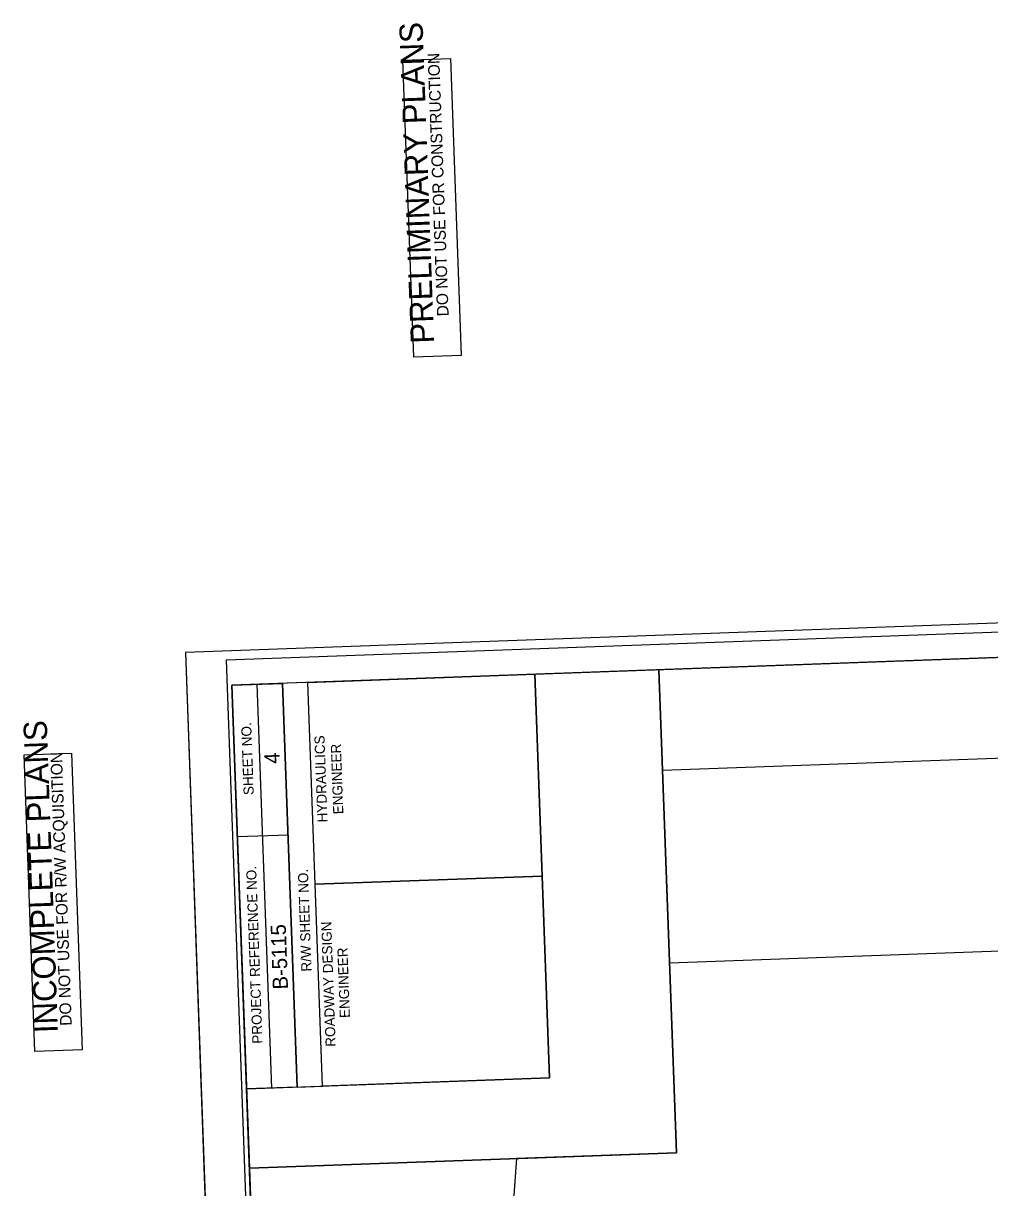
# Model space of a CAD drawing. Extents: x 2065068 to 2066582, y 144283 to 146300.
# Drawn here: x 2065347 to 2065825, y 145724 to 146300 of the extents above; entities that cross this region are included whole.
import ezdxf

# ---------------------------------------------------------------- set-up
doc = ezdxf.new("R2010")
doc.units = 0
for name, color, linetype in [('Sheet Clip Boundary CELL', 7, 'Continuous'), ('Sheet Cutting Line CELL', 7, 'Continuous'), ('Sheet Data Field CELL', 7, 'Continuous'), ('Sheet Layout Plan Border', 7, 'Continuous'), ('Sheet Plan CELL', 7, 'Continuous'), ('Sheet Plan Layout CELL', 7, 'Continuous'), ('Sheet Plot Border Inside CELL', 7, 'Continuous'), ('Sheet Plot Border Outside CELL', 7, 'Continuous'), ('Sheet Sticker Incomplete CELL', 7, 'Continuous'), ('Sheet Sticker Preliminary CELL', 7, 'Continuous')]:
    doc.layers.add(name, color=color, linetype=linetype)

msp = doc.modelspace()

# ---------------------------------------------------------------- linework, layer by layer
at = {"layer": 'Sheet Clip Boundary CELL'}
msp.add_lwpolyline([(2066209.26, 144563.12), (2066197.36, 145017.22), (2066304.56, 145076.85), (2066276.35, 145857.16), (2065667.01, 145835.13), (2065670.41, 145741.24), (2065591.32, 145738.38), (2065521, 144770.65), (2065527.51, 144606.5), (2065634.3, 144549.42)], close=True, dxfattribs=at)
at = {"layer": 'Sheet Cutting Line CELL'}
msp.add_line((2065427.33, 145988.88), (2065488.14, 144306.48), dxfattribs=at)
at = {"layer": 'Sheet Layout Plan Border'}
msp.add_lwpolyline([(2066552.11, 144561.57), (2066501.53, 145960.67), (2065663.57, 145930.38), (2065670.41, 145741.24), (2065459.06, 145733.6), (2065502.79, 144523.64)], close=True, dxfattribs=at)
at = {"layer": 'Sheet Plan CELL'}
for p, q in [((2065470.17, 145773.23), (2065462.95, 145973.15)), ((2065482.7, 145773.69), (2065475.45, 145973.6)), ((2065482.7, 145773.69), (2065475.45, 145973.6)), ((2065453.19, 145897.72), (2065478.17, 145898.68)), ((2065491.56, 145874.13), (2065603.95, 145878.21)), ((2065482.7, 145773.69), (2065495.18, 145774.15))]:
    msp.add_line(p, q, dxfattribs=at)
for points in [[(2065450.41, 145972.73), (2065504.6, 144473.67), (2066553.91, 144511.61), (2066499.73, 146010.64)], [(2066553.91, 144511.61), (2065504.63, 144473.65), (2065457.63, 145772.79), (2065607.59, 145778.22), (2065600.38, 145978.13), (2066499.73, 146010.64)], [(2065457.63, 145772.79), (2065450.41, 145972.73), (2065475.45, 145973.6), (2065482.7, 145773.69)], [(2065491.56, 145874.13), (2065487.94, 145974.05), (2065600.38, 145978.13), (2065604, 145878.2)], [(2065495.18, 145774.15), (2065491.56, 145874.13), (2065604, 145878.2), (2065607.59, 145778.22)]]:
    msp.add_lwpolyline(points, close=True, dxfattribs=at)
at = {"layer": 'Sheet Plan Layout CELL'}
for points in [[(2065504.63, 144473.65), (2066553.91, 144511.61), (2066499.73, 146010.63), (2065661.76, 145980.34), (2065670.41, 145741.24), (2065459.06, 145733.6)], [(2065670.41, 145741.24), (2065661.76, 145980.36), (2065450.41, 145972.75), (2065459.06, 145733.6)]]:
    msp.add_lwpolyline(points, close=True, dxfattribs=at)
at = {"layer": 'Sheet Plot Border Inside CELL'}
msp.add_lwpolyline([(2066561.97, 144358.31), (2066501.77, 146023.21), (2065447.47, 145985.11), (2065507.66, 144320.2)], close=True, dxfattribs=at)
at = {"layer": 'Sheet Plot Border Outside CELL'}
msp.add_lwpolyline([(2066582.43, 144346.04), (2066521.61, 146028.44), (2065427.33, 145988.88), (2065488.14, 144306.48)], close=True, dxfattribs=at)
at = {"layer": 'Sheet Sticker Incomplete CELL'}
msp.add_lwpolyline([(2065376.31, 145792.14), (2065352.82, 145791.29), (2065347.51, 145938.19), (2065371, 145939.04)], close=True, dxfattribs=at)
at = {"layer": 'Sheet Sticker Preliminary CELL'}
msp.add_lwpolyline([(2065563.83, 146135.98), (2065540.35, 146135.13), (2065535.04, 146282.04), (2065558.52, 146282.89)], close=True, dxfattribs=at)

# ---------------------------------------------------------------- texts
at = {"layer": 'Sheet Data Field CELL'}
for s, p in [('4', (2065474.08, 145933.87)), ('B-5115', (2065478.18, 145822.16))]:
    msp.add_text(s, height=7.5, rotation=92.07025, dxfattribs=at).set_placement(p)
at = {"layer": 'Sheet Plan CELL'}
for s, height, p in [('SHEET NO.', 5, (2065461.21, 145918.38)), ('HYDRAULICS', 5, (2065497.73, 145904.84)), ('ENGINEER', 5, (2065505.55, 145908.88)), ('PROJECT REFERENCE NO.', 5.0001, (2065465.54, 145795.29)), ('R/W SHEET NO.', 5.0001, (2065489.82, 145830.99)), ('ROADWAY DESIGN', 5.0001, (2065501.77, 145793.77)), ('ENGINEER', 5, (2065508.8, 145808.02))]:
    msp.add_text(s, height=height, rotation=92.07025, dxfattribs=at).set_placement(p)
at = {"layer": 'Sheet Sticker Incomplete CELL'}
for s, height, p in [('INCOMPLETE PLANS', 11.52, (2065364.29, 145800.66)), ('DO NOT USE FOR R/W ACQUISITION', 5.76, (2065371.12, 145804.16))]:
    msp.add_text(s, height=height, rotation=92.07024, dxfattribs=at).set_placement(p)
at = {"layer": 'Sheet Sticker Preliminary CELL'}
for s, height, p in [('PRELIMINARY PLANS', 11.52, (2065550.46, 146142)), ('DO NOT USE FOR CONSTRUCTION', 5.76, (2065557.68, 146155.37))]:
    msp.add_text(s, height=height, rotation=92.07024, dxfattribs=at).set_placement(p)

doc.saveas('drawing.dxf')
